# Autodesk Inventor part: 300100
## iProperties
Created: 2007-11
Part Number: 300100
Document SubType Name: Modeling
Designer: TH
Density: 8.08 g/cm^3
Mass: 7.827 g
Surface Area: 19.058 cm^2
Volume: 0.968688 cm^3
Material: Stainless Steel
Description: WIRE MIDDLE
Component Category: Back Component
Author: TH
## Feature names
1. Extrusion1
2. Coil1
3. Extrusion2
4. Fillet1
5. Mirror1
